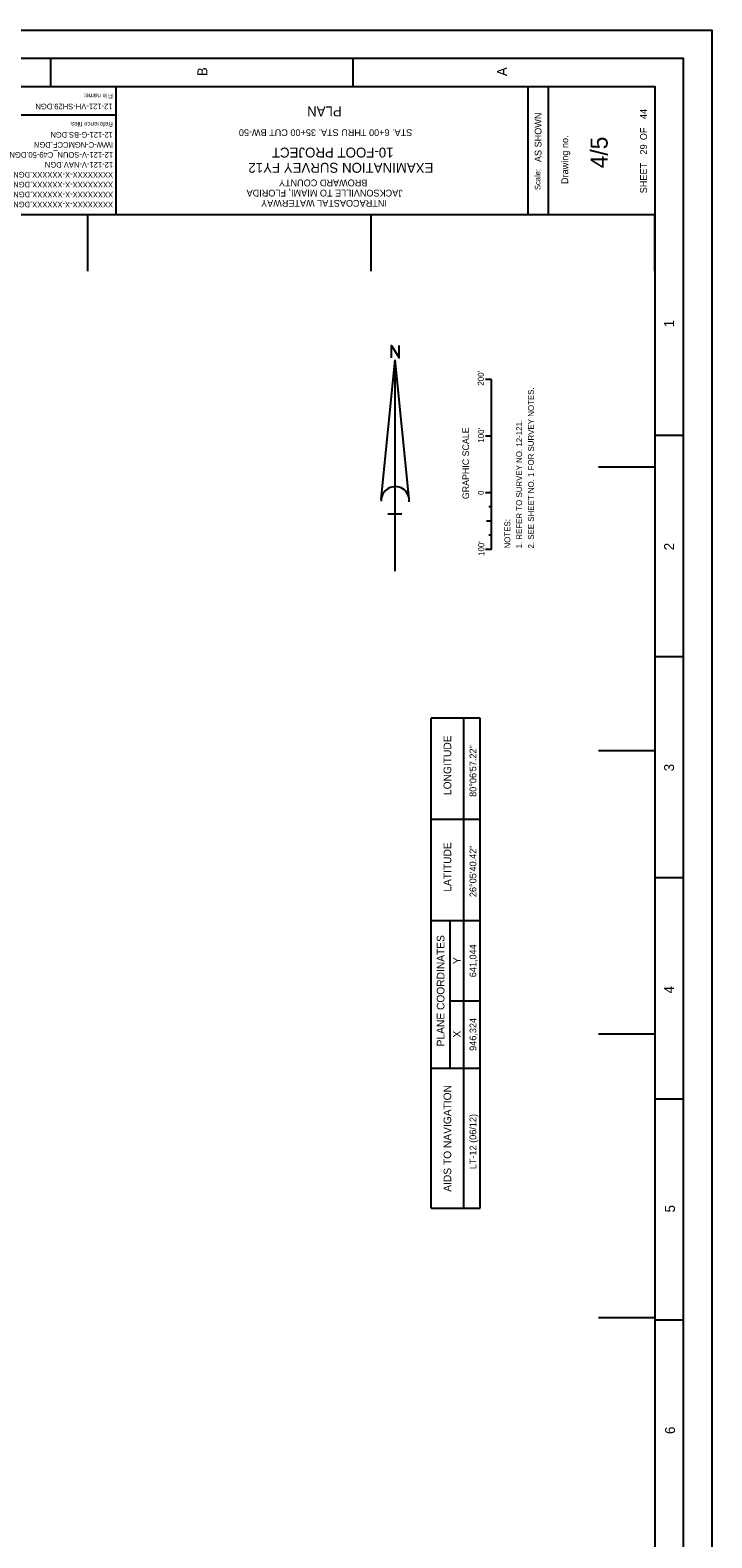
# Model space of a CAD drawing. Extents: x 944701 to 948101, y 637871 to 642271.
# Drawn here: x 946898 to 948101, y 639612 to 642271 of the extents above; entities that cross this region are included whole.
import ezdxf

# ---------------------------------------------------------------- set-up
doc = ezdxf.new("R2010")
doc.units = 0
for name, color, linetype in [('G-ANNO-NPLT', 7, 'Continuous'), ('G-ANNO-TEXT-DRWG', 7, 'Continuous'), ('G-ANNO-TEXT-PROJ', 7, 'Continuous'), ('G-ANNO-TEXT-TTLB', 7, 'Continuous'), ('G-ANNO-TTLB', 7, 'Continuous'), ('V-ANNO-NOTE', 7, 'Continuous'), ('V-ANNO-SCHD', 7, 'Continuous'), ('V-ANNO-SYMB', 7, 'Continuous'), ('V-TOPO-COOR-STAT', 7, 'Continuous')]:
    doc.layers.add(name, color=color, linetype=linetype)

msp = doc.modelspace()

# ---------------------------------------------------------------- linework, layer by layer
at = {"layer": 'G-ANNO-NPLT'}
msp.add_lwpolyline([(944700.8, 637870.8), (944700.8, 642270.8), (948100.8, 642270.8), (948100.8, 637870.8)], close=True, dxfattribs=at)
msp.add_lwpolyline([(948050.8, 642270.9), (948100.8, 642270.9), (948100.8, 642220.9)], dxfattribs=at)
at = {"layer": 'G-ANNO-TTLB'}
for p, q in [((946934.2, 642220.8), (946934.2, 642170.8)), ((947467.5, 642220.8), (947467.5, 642170.8)), ((947050, 641945.7), (947050, 642170.8)), ((947777, 641945.7), (947777, 642170.8)), ((947812.7, 641945.7), (947812.7, 642170.8)), ((946698.7, 642121.5), (947050, 642121.5)), ((944800.8, 641945.7), (948000.8, 641945.7)), ((948050.8, 641555.8), (948000.8, 641555.8)), ((948050.8, 641165.8), (948000.8, 641165.8)), ((948050.8, 640775.8), (948000.8, 640775.8)), ((948050.8, 640385.8), (948000.8, 640385.8)), ((948050.8, 639995.8), (948000.8, 639995.8))]:
    msp.add_line(p, q, dxfattribs=at)
for points in [[(948050.8, 637920.8), (948050.8, 642220.8), (944750.8, 642220.8), (944750.8, 637920.8)], [(944800.8, 642170.8), (944800.8, 638045.8), (948000.8, 638045.8), (948000.8, 642170.8)]]:
    msp.add_lwpolyline(points, close=True, dxfattribs=at)
at = {"layer": 'V-ANNO-NOTE'}
for p, q in [((947712, 641655), (947701.6, 641655)), ((947712, 641355), (947712, 641655)), ((947712, 641555), (947701.6, 641555)), ((947712, 641455), (947701.6, 641455)), ((947712, 641455), (947701.6, 641455)), ((947712, 641455), (947707.1, 641455)), ((947712, 641430), (947707.3, 641430)), ((947712, 641405), (947703.5, 641405)), ((947712, 641380), (947707.3, 641380)), ((947712, 641355), (947701.6, 641355))]:
    msp.add_line(p, q, dxfattribs=at)
at = {"layer": 'V-ANNO-SCHD'}
for p, q in [((947605.5, 640193.5), (947605.5, 641057.5)), ((947692.1, 641057.5), (947605.5, 641057.5)), ((947663.2, 640193.5), (947663.2, 641057.5)), ((947692.1, 640193.5), (947692.1, 641057.5)), ((947605.5, 640879.2), (947692.1, 640879.2)), ((947605.5, 640700.9), (947692.1, 640700.9)), ((947639.2, 640440.2), (947639.2, 640700.9)), ((947639.2, 640559), (947692.1, 640559)), ((947605.5, 640440.2), (947692.1, 640440.2)), ((947605.5, 640193.5), (947692.1, 640193.5))]:
    msp.add_line(p, q, dxfattribs=at)
at = {"layer": 'V-ANNO-SYMB'}
for p, q in [((947517.7, 641443.6), (947542.4, 641689.3)), ((947542.4, 641317), (947542.4, 641689.3)), ((947567.1, 641443.6), (947542.4, 641689.3)), ((947554.2, 641417.5), (947529.4, 641417.5))]:
    msp.add_line(p, q, dxfattribs=at)
msp.add_lwpolyline([(947535.5, 641693.3), (947535.5, 641715), (947549.1, 641693.3), (947549.1, 641715)], dxfattribs=at)
msp.add_arc((947542.4, 641441.1), 24.8, 355.2984, 182.0673, dxfattribs=at)
at = {"layer": 'V-TOPO-COOR-STAT'}
for p, q in [((947000, 641845.7), (947000, 641945.7)), ((947500, 641845.7), (947500, 641945.7)), ((948000, 641845.7), (948000, 641945.7)), ((948000.8, 641500), (947900.8, 641500)), ((948000.8, 641000), (947900.8, 641000)), ((948000.8, 640500), (947900.8, 640500)), ((948000.8, 640000), (947900.8, 640000))]:
    msp.add_line(p, q, dxfattribs=at)

# ---------------------------------------------------------------- texts
at = {"layer": 'G-ANNO-TEXT-DRWG'}
for s, height, rotation, p in [('12-121-VH-SH29.DGN', 10, 180, (947043.6, 642141.2)), ('PLAN', 17.5, 180, (947448, 642136.3)), (' 29          44', 12, 90, (947986.3, 642047.2)), ('STA. 6+00 THRU STA. 35+00 CUT BW-50', 12, 180, (947572.4, 642096.1)), ('IWW-C-NGMCCF.DGN', 10, 180, (947044.7, 642073.5)), ('4/5', 30, 90, (947917, 642027.3)), ('12-121-V-SOUN_C49-50.DGN', 10, 180, (947044.7, 642056)), ('12-121-V-NAV.DGN', 10, 180, (947044.7, 642038.5)), ('XXXXXXXX-X-XXXXXX.DGN', 10, 180, (947044.7, 642021)), ('XXXXXXXX-X-XXXXXX.DGN', 10, 180, (947044.7, 642003.5)), ('XXXXXXXX-X-XXXXXX.DGN', 10, 180, (947044.7, 641986)), ('XXXXXXXX-X-XXXXXX.DGN', 10, 180, (947044.7, 641968.5))]:
    msp.add_text(s, height=height, rotation=rotation, dxfattribs=at).set_placement(p)
at = {"layer": 'G-ANNO-TEXT-PROJ'}
for s, height, p in [('12-121-G-BS.DGN', 9.8, (947044.3, 642091.2)), ('10-FOOT PROJECT', 17.5, (947539.3, 642063.8)), ('EXAMINATION SURVEY FY12', 17.5, (947609.7, 642036.9)), ('BROWARD COUNTY', 12, (947493.2, 642007.5)), ('JACKSONVILLE TO MIAMI, FLORIDA', 12, (947555.7, 641989.5)), ('INTRACOASTAL WATERWAY', 12, (947527.7, 641971.5))]:
    msp.add_text(s, height=height, rotation=180, dxfattribs=at).set_placement(p)
at = {"layer": 'G-ANNO-TEXT-TTLB'}
for s, height, rotation, p in [('File name:', 8, 180, (947044, 642158.8)), ('AS SHOWN', 12, 90, (947800.3, 642038.2)), ('Reference files:', 8, 180, (947044.2, 642108.9)), ('SHEET         OF', 12, 90, (947986.3, 641983.2)), ('Drawing no.', 12, 90, (947847.4, 641999.6)), ('Scale:', 10, 90, (947798.4, 641988.9))]:
    msp.add_text(s, height=height, rotation=rotation, dxfattribs=at).set_placement(p)
at = {"layer": 'G-ANNO-TTLB'}
for s, p in [('B', (947210.9, 642189.8)), ('A', (947739.6, 642189.8)), ('1', (948034.1, 641746.8)), ('2', (948034.1, 641353.7)), ('3', (948034.1, 640963.9)), ('4', (948034.1, 640572.1)), ('5', (948035.8, 640185.9)), ('6', (948035.8, 639795.1))]:
    msp.add_text(s, height=17.5, rotation=90, dxfattribs=at).set_placement(p)
at = {"layer": 'V-ANNO-NOTE'}
for s, height, p in [("200'", 10.42, (947698.4, 641644)), ('2. SEE SHEET NO. 1 FOR SURVEY NOTES.', 10.416, (947787, 641356.8)), ('1. REFER TO SURVEY NO. 12-121.', 10.416, (947766.1, 641356.8)), ('GRAPHIC SCALE', 11.666, (947672.5, 641443.8)), ("100'", 10.42, (947698.9, 641543.4)), ('0', 10.4, (947698.6, 641451.3)), ('NOTES:', 10.42, (947745.3, 641356.8)), ("100'", 10.42, (947699.3, 641343.7))]:
    msp.add_text(s, height=height, rotation=90, dxfattribs=at).set_placement(p)
at = {"layer": 'V-ANNO-SCHD'}
for s, height, p in [('LONGITUDE', 13.47, (947641.1, 640922)), ('LATITUDE', 13.47, (947641.1, 640751.6)), ('PLANE COORDINATES', 13.471, (947629.1, 640478.8)), ('Y', 13.5, (947657.9, 640624)), ('X', 13.5, (947657.9, 640494.3)), ('AIDS TO NAVIGATION', 13.471, (947641.1, 640222.4))]:
    msp.add_text(s, height=height, rotation=90.0001, dxfattribs=at).set_placement(p)
at = {"layer": 'V-ANNO-SYMB'}
for s, p in [('80%%D06\'57.22"', (947685.4, 640918.8)), ('26%%D05\'40.42"', (947685.4, 640742)), ('641,044', (947685.4, 640600.7)), ('946,324', (947685.4, 640470.9)), ('LT-12 (06/12)', (947685.4, 640262.3))]:
    msp.add_text(s, height=12, rotation=90, dxfattribs=at).set_placement(p)

doc.saveas('drawing.dxf')
